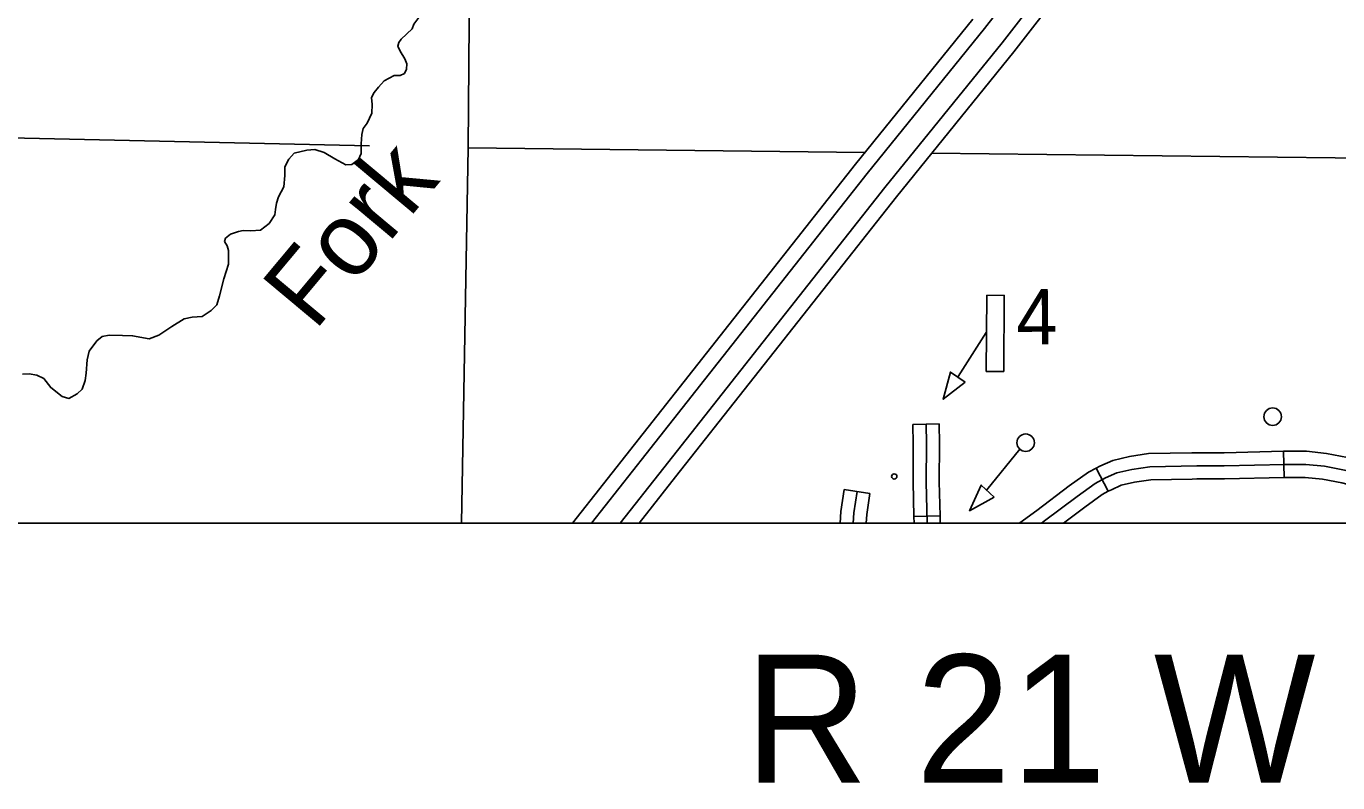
# Model space of a CAD drawing. Extents: x 1369979 to 1371646, y 379997 to 381064.
# Drawn here: x 1370824.5 to 1370912.7, y 380128.9 to 380179.8 of the extents above; entities that cross this region are included whole.
import ezdxf

# ---------------------------------------------------------------- set-up
doc = ezdxf.new("R2010")
doc.units = 0
for name, color, linetype in [('Default', 7, 'Continuous'), ('R_Border Notes', 7, 'Continuous'), ('R_No Plot', 7, 'Continuous')]:
    doc.layers.add(name, color=color, linetype=linetype)

msp = doc.modelspace()

# ---------------------------------------------------------------- linework, layer by layer
at = {"layer": 'R_Border Notes'}
for p, q in [((1370887.173, 380156.253), (1370889.062, 380159.218)), ((1370884.127, 380153.026), (1370885.884, 380153.061)), ((1370889.098, 380148.633), (1370891.312, 380151.364)), ((1370909.116, 380149.463), (1370909.071, 380151.22)), ((1370902.893, 380151.112), (1370902.893, 380151.112)), ((1370896.458, 380150.091), (1370897.268, 380148.531)), ((1370879.496, 380148.644), (1370881.236, 380148.393)), ((1370884.192, 380146.837), (1370885.949, 380146.877))]:
    msp.add_line(p, q, dxfattribs=at)
for points in [[(1370854.557, 380216.615), (1370854.188, 380171.633)], [(1370895.552, 380188.173), (1370888.941, 380179.667)], [(1370890.128, 380178.712), (1370896.751, 380187.233)], [(1370890.905, 380178.088), (1370897.534, 380186.618)], [(1370852.401, 380184.432), (1370853.155, 380184.121), (1370853.288, 380183.943), (1370853.51, 380183.455), (1370853.421, 380182.863), (1370852.83, 380182.242), (1370852.549, 380181.857), (1370852.446, 380181.517), (1370852.15, 380181.191), (1370851.515, 380180.851), (1370850.953, 380180.496), (1370850.539, 380179.963), (1370850.435, 380179.638)], [(1370880.257, 380170.534), (1370888.165, 380180.291)], [(1370850.435, 380179.638), (1370849.685, 380178.953), (1370849.522, 380178.731), (1370849.463, 380178.48), (1370849.625, 380178.139), (1370849.936, 380177.636), (1370850.069, 380177.296), (1370850.054, 380176.941), (1370849.906, 380176.63), (1370849.625, 380176.512), (1370849.212, 380176.512), (1370848.532, 380176.142), (1370848.162, 380175.728), (1370847.881, 380175.358), (1370847.689, 380175.018), (1370847.733, 380174.544), (1370847.704, 380173.967), (1370847.408, 380173.286), (1370847.127, 380172.931), (1370847.039, 380172.532), (1370846.994, 380171.911)], [(1370888.941, 380179.667), (1370881.038, 380169.916)], [(1370882.232, 380168.97), (1370890.128, 380178.712)], [(1370883.013, 380168.352), (1370890.905, 380178.088)], [(1370792.037, 380173.006), (1370847.558, 380171.779)], [(1370846.994, 380171.911), (1370846.997, 380171.255), (1370846.82, 380170.856), (1370846.376, 380170.515), (1370845.963, 380170.501), (1370845.223, 380170.9), (1370844.499, 380171.329), (1370843.878, 380171.521), (1370843.346, 380171.477), (1370842.489, 380171.285), (1370842.119, 380170.87), (1370841.868, 380170.367), (1370841.868, 380169.776), (1370841.794, 380169.021), (1370841.439, 380168.341), (1370841.306, 380167.926), (1370841.232, 380167.482), (1370841.188, 380167.127), (1370840.804, 380166.55), (1370840.227, 380166.106), (1370839.577, 380166.047), (1370839.06, 380166.077), (1370838.749, 380166.018), (1370838.202, 380165.84), (1370837.862, 380165.559), (1370837.803, 380165.337)], [(1370854.188, 380171.633), (1370853.739, 380146.391)], [(1370854.188, 380171.633), (1370880.895, 380171.322)], [(1370885.378, 380171.27), (1370916.415, 380170.909)], [(1370865.393, 380151.673), (1370880.257, 380170.534)], [(1370881.038, 380169.916), (1370866.176, 380151.057)], [(1370867.373, 380150.115), (1370882.232, 380168.97)], [(1370868.156, 380149.499), (1370883.013, 380168.352)], [(1370837.803, 380165.337), (1370837.969, 380165.05), (1370838.057, 380164.725), (1370838.072, 380163.822), (1370837.747, 380162.831), (1370837.451, 380161.677), (1370837.274, 380161.07), (1370836.904, 380160.686), (1370836.298, 380160.286), (1370835.633, 380160.242), (1370835.086, 380160.123), (1370834.259, 380159.62), (1370833.387, 380159.043), (1370832.736, 380158.792), (1370831.613, 380158.999), (1370830.933, 380159.014), (1370830.046, 380159.029), (1370829.558, 380158.94), (1370829.218, 380158.644), (1370828.686, 380157.963), (1370828.553, 380157.372)], [(1370828.553, 380157.372), (1370828.486, 380156.468), (1370828.413, 380155.979), (1370828.22, 380155.402), (1370827.895, 380155.077), (1370827.333, 380154.781), (1370826.875, 380154.914), (1370826.107, 380155.506), (1370825.634, 380156.112), (1370825.161, 380156.349), (1370824.658, 380156.423), (1370824.2, 380156.408)], [(1370884.127, 380153.026), (1370884.153, 380151.722), (1370884.14, 380149.141), (1370884.192, 380146.837)], [(1370885.006, 380153.044), (1370885.032, 380151.728), (1370885.019, 380149.149), (1370885.081, 380146.391)], [(1370885.884, 380153.061), (1370885.911, 380151.735), (1370885.898, 380149.157), (1370885.949, 380146.877)], [(1370861.225, 380146.391), (1370865.393, 380151.673)], [(1370909.071, 380151.22), (1370905.066, 380151.118), (1370903.222, 380151.118), (1370902.893, 380151.112)], [(1370909.071, 380151.22), (1370909.152, 380151.222), (1370910.614, 380151.222), (1370911.947, 380151.083), (1370913.362, 380150.811), (1370915.402, 380150.294)], [(1370866.176, 380151.057), (1370862.494, 380146.391)], [(1370892.785, 380146.391), (1370892.984, 380146.54), (1370895.17, 380148.181), (1370896.393, 380149.067), (1370897.096, 380149.431), (1370897.85, 380149.77), (1370898.865, 380150.004), (1370900.062, 380150.187), (1370903.23, 380150.239), (1370905.078, 380150.239), (1370909.163, 380150.343), (1370910.569, 380150.343), (1370911.818, 380150.213), (1370913.171, 380149.952), (1370915.331, 380149.405), (1370917.309, 380148.806), (1370920.224, 380147.973), (1370923.053, 380147.165), (1370925.614, 380146.391)], [(1370902.893, 380151.112), (1370899.989, 380151.065), (1370898.7, 380150.868), (1370897.569, 380150.607), (1370896.713, 380150.223), (1370896.458, 380150.091)], [(1370864.434, 380146.391), (1370867.373, 380150.115)], [(1370865.703, 380146.391), (1370868.156, 380149.499)], [(1370891.325, 380146.399), (1370892.457, 380147.243), (1370894.648, 380148.888), (1370895.93, 380149.817), (1370896.458, 380150.091)], [(1370902.922, 380149.355), (1370903.237, 380149.36), (1370905.089, 380149.36), (1370909.116, 380149.463)], [(1370909.116, 380149.463), (1370909.175, 380149.464), (1370910.523, 380149.464), (1370911.689, 380149.343), (1370912.98, 380149.094), (1370914.97, 380148.59)], [(1370879.496, 380148.644), (1370879.283, 380147.168), (1370879.225, 380146.391)], [(1370880.366, 380148.518), (1370880.157, 380147.073), (1370880.107, 380146.391)], [(1370894.25, 380146.391), (1370895.691, 380147.474), (1370896.856, 380148.317), (1370897.268, 380148.531)], [(1370897.268, 380148.531), (1370897.478, 380148.64), (1370898.132, 380148.933), (1370899.031, 380149.141), (1370900.136, 380149.309), (1370902.922, 380149.355)], [(1370881.236, 380148.393), (1370881.032, 380146.977), (1370880.988, 380146.391)], [(1370884.192, 380146.837), (1370884.202, 380146.391)], [(1370885.949, 380146.877), (1370885.96, 380146.391)], [(1370891.315, 380146.391), (1370891.325, 380146.399)]]:
    msp.add_lwpolyline(points, dxfattribs=at)
for points in [[(1370890.235, 380156.585), (1370889.063, 380156.595), (1370889.104, 380161.721), (1370890.276, 380161.712)], [(1370887.647, 380155.884), (1370886.652, 380156.547), (1370886.156, 380154.723)], [(1370889.6, 380148.127), (1370888.728, 380148.945), (1370887.938, 380147.228)]]:
    msp.add_lwpolyline(points, close=True, dxfattribs=at)
for centre, radius in [((1370908.333, 380153.551), 0.586), ((1370891.711, 380151.8), 0.586), ((1370882.871, 380149.528), 0.176)]:
    msp.add_circle(centre, radius, dxfattribs=at)
at = {"layer": 'R_No Plot'}
msp.add_lwpolyline([(1370544.495, 380586.867), (1371140.383, 380586.867), (1371140.383, 380146.391), (1370544.495, 380146.391)], close=True, dxfattribs=at)

# ---------------------------------------------------------------- texts
at = {"layer": 'Default'}
msp.add_text('R 21 W', height=8.6181, dxfattribs=at).set_placement((1370872.792, 380128.923))
at = {"layer": 'R_Border Notes'}
for s, height, rotation, p in [('Fork', 4.95, 50.11816, (1370843.865, 380159.254)), ('4', 3.712, 0.47793, (1370891.099, 380158.41))]:
    msp.add_text(s, height=height, rotation=rotation, dxfattribs=at).set_placement(p)

doc.saveas('drawing.dxf')
